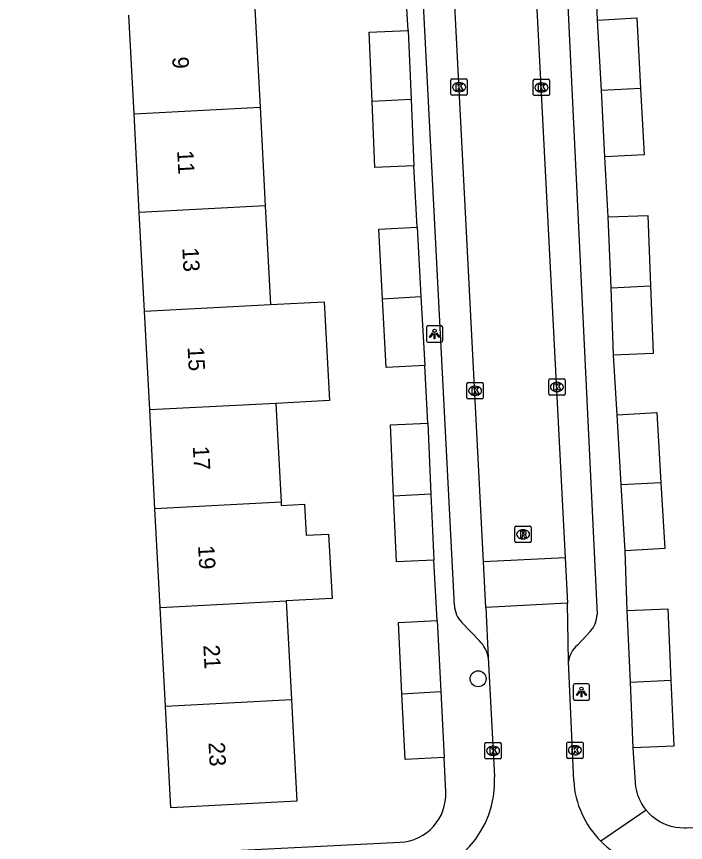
# Model space of a CAD drawing. Extents: x 161084 to 161928, y 385355 to 386522.
# Drawn here: x 161364.7 to 161405.7, y 385655.3 to 385705.9 of the extents above; entities that cross this region are included whole.
import ezdxf

# ---------------------------------------------------------------- set-up
doc = ezdxf.new("R2010")
doc.units = 0
for name, color, linetype in [('IMGEO_Boom', 7, 'Continuous'), ('IMGEO_Kolk', 7, 'Continuous'), ('IMGEO_Lichtpunt', 7, 'Continuous'), ('IMGEO_Pand', 7, 'Continuous'), ('IMGEO_Pand_nummerreeks', 7, 'Continuous'), ('IMGEO_Rijbaan_lokaal_open', 7, 'Continuous'), ('IMGEO_Rioolput', 7, 'Continuous'), ('IMGEO_Voetpad_open', 7, 'Continuous')]:
    doc.layers.add(name, color=color, linetype=linetype)

msp = doc.modelspace()

# ---------------------------------------------------------------- linework, layer by layer
at = {"layer": 'IMGEO_Boom'}
msp.add_circle((161392.96, 385665.309), 0.489, dxfattribs=at)
at = {"layer": 'IMGEO_Kolk'}
for p, q in [((161391.293, 385701.148), (161391.293, 385702)), ((161391.368, 385702.074), (161392.22, 385702.074)), ((161391.781, 385701.854), (161391.806, 385701.854)), ((161392.294, 385702), (161392.294, 385701.148)), ((161396.34, 385701.129), (161396.34, 385701.981)), ((161396.415, 385702.055), (161397.267, 385702.055)), ((161396.828, 385701.835), (161396.853, 385701.835)), ((161397.341, 385701.981), (161397.341, 385701.129)), ((161391.804, 385701.294), (161391.779, 385701.294)), ((161396.851, 385701.275), (161396.826, 385701.275)), ((161392.22, 385701.074), (161391.368, 385701.074)), ((161397.267, 385701.055), (161396.415, 385701.055)), ((161392.269, 385682.538), (161392.269, 385683.39)), ((161392.344, 385683.464), (161393.196, 385683.464)), ((161393.27, 385683.39), (161393.27, 385682.538)), ((161397.288, 385682.767), (161397.288, 385683.619)), ((161397.363, 385683.693), (161398.215, 385683.693)), ((161397.776, 385683.473), (161397.801, 385683.473)), ((161398.289, 385683.619), (161398.289, 385682.767)), ((161392.757, 385683.244), (161392.782, 385683.244)), ((161397.799, 385682.913), (161397.774, 385682.913)), ((161393.196, 385682.464), (161392.344, 385682.464)), ((161392.78, 385682.684), (161392.755, 385682.684)), ((161398.215, 385682.693), (161397.363, 385682.693)), ((161393.376, 385660.471), (161393.376, 385661.323)), ((161393.451, 385661.397), (161394.303, 385661.397)), ((161393.864, 385661.177), (161393.889, 385661.177)), ((161394.377, 385661.323), (161394.377, 385660.471)), ((161398.394, 385660.502), (161398.394, 385661.354)), ((161398.469, 385661.428), (161399.321, 385661.428)), ((161398.882, 385661.208), (161398.907, 385661.208)), ((161399.395, 385661.354), (161399.395, 385660.502)), ((161393.887, 385660.617), (161393.862, 385660.617)), ((161398.905, 385660.648), (161398.88, 385660.648)), ((161394.303, 385660.397), (161393.451, 385660.397)), ((161399.321, 385660.428), (161398.469, 385660.428))]:
    msp.add_line(p, q, dxfattribs=at)
for points in [[(161391.293, 385701.148), (161391.293, 385702)], [(161391.368, 385702.074), (161392.22, 385702.074)], [(161391.614, 385701.774), (161391.737, 385701.774), (161391.737, 385701.623), (161391.867, 385701.774), (161392.031, 385701.774), (161391.885, 385701.623), (161392.038, 385701.374), (161391.886, 385701.374), (161391.801, 385701.538), (161391.737, 385701.471), (161391.737, 385701.374), (161391.614, 385701.374), (161391.614, 385701.774)], [(161392.294, 385702), (161392.294, 385701.148)], [(161396.34, 385701.129), (161396.34, 385701.981)], [(161396.415, 385702.055), (161397.267, 385702.055)], [(161396.661, 385701.755), (161396.784, 385701.755), (161396.784, 385701.604), (161396.914, 385701.755), (161397.078, 385701.755), (161396.932, 385701.604), (161397.085, 385701.355), (161396.933, 385701.355), (161396.848, 385701.519), (161396.784, 385701.452), (161396.784, 385701.355), (161396.661, 385701.355), (161396.661, 385701.755)], [(161397.341, 385701.981), (161397.341, 385701.129)], [(161392.22, 385701.074), (161391.368, 385701.074)], [(161397.267, 385701.055), (161396.415, 385701.055)], [(161392.269, 385682.538), (161392.269, 385683.39)], [(161392.344, 385683.464), (161393.196, 385683.464)], [(161393.27, 385683.39), (161393.27, 385682.538)], [(161397.288, 385682.767), (161397.288, 385683.619)], [(161397.363, 385683.693), (161398.215, 385683.693)], [(161397.609, 385683.393), (161397.732, 385683.393), (161397.732, 385683.242), (161397.862, 385683.393), (161398.026, 385683.393), (161397.88, 385683.242), (161398.033, 385682.993), (161397.881, 385682.993), (161397.796, 385683.157), (161397.732, 385683.09), (161397.732, 385682.993), (161397.609, 385682.993), (161397.609, 385683.393)], [(161398.289, 385683.619), (161398.289, 385682.767)], [(161392.59, 385683.164), (161392.713, 385683.164), (161392.713, 385683.013), (161392.843, 385683.164), (161393.007, 385683.164), (161392.861, 385683.013), (161393.014, 385682.764), (161392.862, 385682.764), (161392.777, 385682.928), (161392.713, 385682.861), (161392.713, 385682.764), (161392.59, 385682.764), (161392.59, 385683.164)], [(161393.196, 385682.464), (161392.344, 385682.464)], [(161398.215, 385682.693), (161397.363, 385682.693)], [(161393.376, 385660.471), (161393.376, 385661.323)], [(161393.451, 385661.397), (161394.303, 385661.397)], [(161394.377, 385661.323), (161394.377, 385660.471)], [(161398.394, 385660.502), (161398.394, 385661.354)], [(161398.469, 385661.428), (161399.321, 385661.428)], [(161398.715, 385661.128), (161398.838, 385661.128), (161398.838, 385660.977), (161398.968, 385661.128), (161399.132, 385661.128), (161398.986, 385660.977), (161399.139, 385660.728), (161398.987, 385660.728), (161398.902, 385660.892), (161398.838, 385660.825), (161398.838, 385660.728), (161398.715, 385660.728), (161398.715, 385661.128)], [(161399.395, 385661.354), (161399.395, 385660.502)], [(161393.697, 385661.097), (161393.82, 385661.097), (161393.82, 385660.946), (161393.95, 385661.097), (161394.114, 385661.097), (161393.968, 385660.946), (161394.121, 385660.697), (161393.969, 385660.697), (161393.884, 385660.861), (161393.82, 385660.794), (161393.82, 385660.697), (161393.697, 385660.697), (161393.697, 385661.097)], [(161394.303, 385660.397), (161393.451, 385660.397)], [(161399.321, 385660.428), (161398.469, 385660.428)]]:
    msp.add_lwpolyline(points, dxfattribs=at)
for centre, start, end in [((161391.37, 385701.998), 91.552, 178.448), ((161391.37, 385701.998), 91.552, 178.448), ((161392.218, 385701.998), 1.552, 88.448), ((161392.218, 385701.998), 1.552, 88.448), ((161396.417, 385701.979), 91.552, 178.448), ((161396.417, 385701.979), 91.552, 178.448), ((161397.265, 385701.979), 1.552, 88.448), ((161397.265, 385701.979), 1.552, 88.448), ((161391.37, 385701.15), 181.552, 268.448), ((161391.37, 385701.15), 181.552, 268.448), ((161392.218, 385701.15), 271.552, 358.448), ((161392.218, 385701.15), 271.552, 358.448), ((161396.417, 385701.131), 181.552, 268.448), ((161396.417, 385701.131), 181.552, 268.448), ((161397.265, 385701.131), 271.552, 358.448), ((161397.265, 385701.131), 271.552, 358.448), ((161392.346, 385683.388), 91.552, 178.448), ((161392.346, 385683.388), 91.552, 178.448), ((161393.194, 385683.388), 1.552, 88.448), ((161393.194, 385683.388), 1.552, 88.448), ((161397.365, 385683.617), 91.552, 178.448), ((161397.365, 385683.617), 91.552, 178.448), ((161398.213, 385683.617), 1.552, 88.448), ((161398.213, 385683.617), 1.552, 88.448), ((161392.346, 385682.54), 181.552, 268.448), ((161392.346, 385682.54), 181.552, 268.448), ((161393.194, 385682.54), 271.552, 358.448), ((161393.194, 385682.54), 271.552, 358.448), ((161397.365, 385682.769), 181.552, 268.448), ((161397.365, 385682.769), 181.552, 268.448), ((161398.213, 385682.769), 271.552, 358.448), ((161398.213, 385682.769), 271.552, 358.448), ((161393.453, 385661.321), 91.552, 178.448), ((161393.453, 385661.321), 91.552, 178.448), ((161394.301, 385661.321), 1.552, 88.448), ((161394.301, 385661.321), 1.552, 88.448), ((161398.471, 385661.352), 91.552, 178.448), ((161398.471, 385661.352), 91.552, 178.448), ((161399.319, 385661.352), 1.552, 88.448), ((161399.319, 385661.352), 1.552, 88.448), ((161393.453, 385660.473), 181.552, 268.448), ((161393.453, 385660.473), 181.552, 268.448), ((161394.301, 385660.473), 271.552, 358.448), ((161394.301, 385660.473), 271.552, 358.448), ((161398.471, 385660.504), 181.552, 268.448), ((161398.471, 385660.504), 181.552, 268.448), ((161399.319, 385660.504), 271.552, 358.448), ((161399.319, 385660.504), 271.552, 358.448)]:
    msp.add_arc(centre, 0.0765, start, end, dxfattribs=at)
for centre, major_axis, ratio, start_param, end_param in [((161391.78, 385701.574), (-0.387, 0.002), 0.722429, 4.712389, 7.853982), ((161391.805, 385701.574), (-0.39, 0.002), 0.717154, 1.570796, 4.712389), ((161396.827, 385701.555), (-0.387, 0.002), 0.722429, 4.712389, 7.853982), ((161396.852, 385701.555), (-0.39, 0.002), 0.717154, 1.570796, 4.712389), ((161397.775, 385683.193), (-0.387, 0.002), 0.722429, 4.712389, 7.853982), ((161397.8, 385683.193), (-0.39, 0.002), 0.717154, 1.570796, 4.712389), ((161392.756, 385682.964), (-0.387, 0.002), 0.722429, 4.712389, 7.853982), ((161392.781, 385682.964), (-0.39, 0.002), 0.717154, 1.570796, 4.712389), ((161393.863, 385660.897), (-0.387, 0.002), 0.722429, 4.712389, 7.853982), ((161393.888, 385660.897), (-0.39, 0.002), 0.717154, 1.570796, 4.712389), ((161398.881, 385660.928), (-0.387, 0.002), 0.722429, 4.712389, 7.853982), ((161398.906, 385660.928), (-0.39, 0.002), 0.717154, 1.570796, 4.712389)]:
    msp.add_ellipse(centre, major_axis=major_axis, ratio=ratio, start_param=start_param, end_param=end_param, dxfattribs=at)
at = {"layer": 'IMGEO_Lichtpunt'}
for p, q in [((161390.694, 385686.939), (161389.886, 385686.939)), ((161390.694, 385686.939), (161389.886, 385686.939)), ((161389.792, 385686.844), (161389.792, 385686.037)), ((161389.792, 385686.844), (161389.792, 385686.037)), ((161390.788, 385686.037), (161390.788, 385686.844)), ((161390.788, 385686.037), (161390.788, 385686.844)), ((161389.886, 385685.943), (161390.694, 385685.943)), ((161389.886, 385685.943), (161390.694, 385685.943)), ((161398.793, 385664.905), (161398.793, 385664.098)), ((161398.793, 385664.905), (161398.793, 385664.098)), ((161399.695, 385665), (161398.887, 385665)), ((161399.695, 385665), (161398.887, 385665)), ((161399.789, 385664.098), (161399.789, 385664.905)), ((161399.789, 385664.098), (161399.789, 385664.905)), ((161398.887, 385664.004), (161399.695, 385664.004)), ((161398.887, 385664.004), (161399.695, 385664.004))]:
    msp.add_line(p, q, dxfattribs=at)
for points in [[(161390.166, 385686.508), (161390.205, 385686.48), (161390.017, 385686.218), (161389.979, 385686.245), (161390.166, 385686.508)], [(161390.268, 385686.46), (161390.315, 385686.46), (161390.315, 385686.138), (161390.268, 385686.138), (161390.268, 385686.46)], [(161390.378, 385686.48), (161390.416, 385686.507), (161390.603, 385686.245), (161390.564, 385686.217), (161390.378, 385686.48)], [(161399.167, 385664.569), (161399.206, 385664.541), (161399.018, 385664.279), (161398.98, 385664.306), (161399.167, 385664.569)], [(161399.269, 385664.521), (161399.316, 385664.521), (161399.316, 385664.199), (161399.269, 385664.199), (161399.269, 385664.521)], [(161399.379, 385664.541), (161399.417, 385664.568), (161399.604, 385664.306), (161399.565, 385664.278), (161399.379, 385664.541)]]:
    msp.add_lwpolyline(points, dxfattribs=at)
for centre in [(161390.291, 385686.642), (161399.292, 385664.703)]:
    msp.add_circle(centre, 0.0994, dxfattribs=at)
for centre, start, end in [((161389.886, 385686.844), 90, 180), ((161389.886, 385686.844), 90, 180), ((161390.694, 385686.844), 0, 90), ((161390.694, 385686.844), 0, 90), ((161389.886, 385686.037), 180, 270), ((161389.886, 385686.037), 180, 270), ((161390.694, 385686.037), 270, 0), ((161390.694, 385686.037), 270, 360), ((161398.887, 385664.905), 90, 180), ((161398.887, 385664.905), 90, 180), ((161399.695, 385664.905), 0, 90), ((161399.695, 385664.905), 0, 90), ((161398.887, 385664.098), 180, 270), ((161398.887, 385664.098), 180, 270), ((161399.695, 385664.098), 270, 0), ((161399.695, 385664.098), 270, 360)]:
    msp.add_arc(centre, 0.0946, start, end, dxfattribs=at)
at = {"layer": 'IMGEO_Pand'}
for points in [[(161379.275, 385706.399), (161379.596, 385700.347)], [(161371.869, 385699.939), (161371.549, 385705.991)], [(161400.284, 385705.685), (161402.687, 385705.811), (161402.914, 385701.486)], [(161400.511, 385701.364), (161400.284, 385705.685)], [(161386.463, 385700.71), (161386.288, 385704.943), (161388.675, 385705.041)], [(161388.675, 385705.041), (161388.849, 385700.836)], [(161402.914, 385701.486), (161400.511, 385701.364)], [(161400.724, 385697.298), (161400.511, 385701.364)], [(161402.914, 385701.486), (161403.127, 385697.424), (161400.724, 385697.298)], [(161386.463, 385700.71), (161388.849, 385700.836)], [(161389.019, 385696.743), (161386.632, 385696.645), (161386.463, 385700.71)], [(161388.849, 385700.836), (161389.019, 385696.743)], [(161371.869, 385699.939), (161379.596, 385700.347)], [(161379.596, 385700.347), (161379.916, 385694.296)], [(161372.189, 385693.888), (161371.869, 385699.939)], [(161379.916, 385694.296), (161372.189, 385693.888)], [(161379.916, 385694.296), (161380.237, 385688.244)], [(161372.51, 385687.836), (161372.189, 385693.888)], [(161400.936, 385693.616), (161403.358, 385693.71), (161403.525, 385689.4)], [(161401.104, 385689.278), (161400.936, 385693.616)], [(161387.099, 385688.606), (161386.868, 385692.866), (161389.224, 385692.993)], [(161389.224, 385692.993), (161389.455, 385688.731)], [(161401.104, 385689.278), (161403.525, 385689.4)], [(161401.264, 385685.149), (161401.104, 385689.278)], [(161403.525, 385689.4), (161403.687, 385685.243), (161401.264, 385685.149)], [(161387.099, 385688.606), (161389.455, 385688.731)], [(161389.684, 385684.509), (161387.328, 385684.382), (161387.099, 385688.606)], [(161389.455, 385688.731), (161389.684, 385684.509)], [(161372.51, 385687.836), (161380.237, 385688.244)], [(161380.237, 385688.244), (161383.52, 385688.418), (161383.84, 385682.366), (161380.557, 385682.192)], [(161372.83, 385681.784), (161372.51, 385687.836)], [(161380.557, 385682.192), (161372.83, 385681.784)], [(161380.557, 385682.192), (161380.878, 385676.141)], [(161373.151, 385675.733), (161372.83, 385681.784)], [(161401.483, 385681.488), (161403.919, 385681.628), (161404.166, 385677.314)], [(161401.729, 385677.191), (161401.483, 385681.488)], [(161387.78, 385676.505), (161387.588, 385680.867), (161389.868, 385680.967)], [(161389.868, 385680.967), (161390.059, 385676.626)], [(161404.166, 385677.314), (161401.729, 385677.191)], [(161401.961, 385673.147), (161401.729, 385677.191)], [(161404.166, 385677.314), (161404.397, 385673.287), (161401.961, 385673.147)], [(161390.059, 385676.626), (161387.78, 385676.505)], [(161390.238, 385672.579), (161387.958, 385672.479), (161387.78, 385676.505)], [(161390.059, 385676.626), (161390.238, 385672.579)], [(161380.878, 385676.141), (161373.151, 385675.733)], [(161380.878, 385676.141), (161380.889, 385675.932), (161382.315, 385676.007), (161382.415, 385674.111), (161383.796, 385674.183), (161384.004, 385670.237), (161381.198, 385670.089)], [(161373.471, 385669.681), (161373.151, 385675.733)], [(161373.471, 385669.681), (161381.198, 385670.089)], [(161381.198, 385670.089), (161381.519, 385664.038)], [(161373.791, 385663.63), (161373.471, 385669.681)], [(161402.098, 385669.486), (161404.579, 385669.595), (161404.771, 385665.228)], [(161402.291, 385665.103), (161402.098, 385669.486)], [(161388.287, 385664.395), (161388.073, 385668.762), (161390.458, 385668.878)], [(161390.458, 385668.878), (161390.671, 385664.521)], [(161402.291, 385665.103), (161404.771, 385665.228)], [(161404.771, 385665.228), (161404.95, 385661.177), (161402.469, 385661.068)], [(161402.469, 385661.068), (161402.291, 385665.103)], [(161388.287, 385664.395), (161390.671, 385664.521)], [(161390.869, 385660.483), (161388.484, 385660.366), (161388.287, 385664.395)], [(161390.671, 385664.521), (161390.869, 385660.483)], [(161381.519, 385664.038), (161381.584, 385662.807), (161381.848, 385657.813), (161374.121, 385657.403), (161373.791, 385663.63)], [(161373.791, 385663.63), (161381.519, 385664.038)]]:
    msp.add_lwpolyline(points, dxfattribs=at)
at = {"layer": 'IMGEO_Rijbaan_lokaal_open'}
for points in [[(161395.274, 385731.281), (161398.285, 385672.728)], [(161393.28, 385672.47), (161390.284, 385730.795)], [(161398.285, 385672.728), (161393.28, 385672.47)], [(161393.423, 385669.684), (161393.28, 385672.47)], [(161398.285, 385672.728), (161398.428, 385669.942)], [(161398.428, 385669.942), (161393.423, 385669.684)], [(161398.5, 385666.359), (161398.428, 385669.942)], [(161393.423, 385669.684), (161393.58, 385666.612)], [(161393.58, 385666.612), (161393.956, 385659.301)], [(161398.817, 385659.048), (161398.5, 385666.359)]]:
    msp.add_lwpolyline(points, dxfattribs=at)
for centre, radius, start, end in [((161388.005, 385659.009), 5.958, 273.248, 2.808), ((161404.516, 385659.389), 5.709, 183.4224, 224.9026), ((161404.514, 385659.385), 5.705, 224.8914, 266.3452)]:
    msp.add_arc(centre, radius, start, end, dxfattribs=at)
at = {"layer": 'IMGEO_Rioolput'}
for p, q in [((161395.211, 385673.738), (161395.211, 385674.59)), ((161395.286, 385674.664), (161396.138, 385674.664)), ((161395.699, 385674.444), (161395.724, 385674.444)), ((161396.212, 385674.59), (161396.212, 385673.738)), ((161395.722, 385673.884), (161395.697, 385673.884)), ((161396.138, 385673.664), (161395.286, 385673.664))]:
    msp.add_line(p, q, dxfattribs=at)
for points in [[(161395.211, 385673.738), (161395.211, 385674.59)], [(161395.286, 385674.664), (161396.138, 385674.664)], [(161395.8, 385674.362), (161395.548, 385674.364), (161395.548, 385673.964)], [(161395.726, 385674.283), (161395.672, 385674.283), (161395.672, 385674.202)], [(161396.212, 385674.59), (161396.212, 385673.738)], [(161395.548, 385673.964), (161395.672, 385673.964), (161395.672, 385674.126), (161395.683, 385674.126)], [(161395.672, 385674.202), (161395.724, 385674.202)], [(161395.73, 385674.097), (161395.801, 385673.964), (161395.941, 385673.964), (161395.876, 385674.09)], [(161396.138, 385673.664), (161395.286, 385673.664)]]:
    msp.add_lwpolyline(points, dxfattribs=at)
for centre, radius, start, end in [((161395.288, 385674.588), 0.0765, 91.552, 178.448), ((161395.288, 385674.588), 0.0765, 91.552, 178.448), ((161395.732, 385674.187), 0.0964, 77.0061, 93.1865), ((161395.746, 385674.244), 0.0378, 276.6634, 79.6772), ((161395.799, 385674.252), 0.109, 350.3612, 89.416), ((161396.136, 385674.588), 0.0765, 1.552, 88.448), ((161396.136, 385674.588), 0.0765, 1.552, 88.448), ((161395.682, 385674.073), 0.0533, 26.0293, 88.6989), ((161395.708, 385674.391), 0.19, 274.7715, 282.9687), ((161395.797, 385674.252), 0.112, 277.5842, 350.9817), ((161395.781, 385674.037), 0.108, 29.5134, 73.7905), ((161395.288, 385673.74), 0.0765, 181.552, 268.448), ((161395.288, 385673.74), 0.0765, 181.552, 268.448), ((161396.136, 385673.74), 0.0765, 271.552, 358.448), ((161396.136, 385673.74), 0.0765, 271.552, 358.448)]:
    msp.add_arc(centre, radius, start, end, dxfattribs=at)
for centre, major_axis, ratio, start_param, end_param in [((161395.698, 385674.164), (-0.387, 0.002), 0.722429, 4.712389, 7.853982), ((161395.723, 385674.164), (-0.39, 0.002), 0.717154, 1.570796, 4.712389)]:
    msp.add_ellipse(centre, major_axis=major_axis, ratio=ratio, start_param=start_param, end_param=end_param, dxfattribs=at)
at = {"layer": 'IMGEO_Voetpad_open'}
for points in [[(161395.274, 385731.281), (161395.294, 385731.127), (161395.327, 385730.976), (161395.374, 385730.828), (161395.434, 385730.685), (161395.506, 385730.548), (161395.59, 385730.418), (161395.686, 385730.296), (161395.76, 385730.215), (161396.868, 385729.068), (161396.987, 385728.933), (161397.093, 385728.789), (161397.186, 385728.635), (161397.264, 385728.475), (161397.328, 385728.307), (161397.377, 385728.135), (161397.41, 385727.959), (161397.427, 385727.781), (161400.248, 385669.245)], [(161391.505, 385669.795), (161388.519, 385727.644)], [(161400.284, 385705.685), (161400.127, 385709.302)], [(161388.675, 385705.041), (161388.436, 385708.777)], [(161400.936, 385693.616), (161400.724, 385697.298)], [(161389.224, 385692.993), (161389.019, 385696.743)], [(161401.483, 385681.488), (161401.264, 385685.149)], [(161389.868, 385680.967), (161389.684, 385684.509)], [(161402.098, 385669.486), (161401.961, 385673.147)], [(161390.458, 385668.878), (161390.238, 385672.579)], [(161393.053, 385667.628), (161391.954, 385668.765)], [(161399.819, 385668.208), (161399.043, 385667.379)], [(161403.264, 385657.253), (161403.107, 385657.466), (161402.969, 385657.692), (161402.852, 385657.929), (161402.756, 385658.177), (161402.683, 385658.431), (161402.633, 385658.691), (161402.607, 385658.955), (161402.469, 385661.068)], [(161390.975, 385658.38), (161390.869, 385660.483)], [(161403.264, 385657.253), (161400.472, 385655.359)], [(161423.333, 385657.052), (161413.445, 385656.551), (161405.714, 385656.16), (161405.58, 385656.156), (161405.316, 385656.167), (161405.053, 385656.201), (161404.794, 385656.258), (161404.542, 385656.339), (161404.298, 385656.441), (161404.063, 385656.565), (161403.841, 385656.709), (161403.633, 385656.873), (161403.44, 385657.055), (161403.264, 385657.253)], [(161362.696, 385656.941), (161362.721, 385656.681), (161362.769, 385656.425), (161362.839, 385656.174), (161362.932, 385655.93), (161363.046, 385655.696), (161363.181, 385655.473), (161363.335, 385655.262), (161363.507, 385655.067), (161363.696, 385654.887), (161363.9, 385654.725), (161364.118, 385654.582), (161364.348, 385654.459), (161364.588, 385654.357), (161364.836, 385654.277), (161365.091, 385654.219), (161365.349, 385654.184), (161365.609, 385654.173), (161365.749, 385654.176), (161379.269, 385654.847), (161388.176, 385655.289)]]:
    msp.add_lwpolyline(points, dxfattribs=at)
for centre, radius, start, end in [((161393.1, 385669.877), 1.597, 182.9541, 224.1528), ((161398.747, 385669.259), 1.501, 315.5778, 359.4731), ((161391.596, 385666.228), 2.02, 10.9616, 43.87), ((161400.079, 385666.173), 1.59, 130.6585, 173.284), ((161388.027, 385658.237), 2.952, 272.8989, 2.7774)]:
    msp.add_arc(centre, radius, start, end, dxfattribs=at)

# ---------------------------------------------------------------- texts
at = {"layer": 'IMGEO_Pand_nummerreeks'}
for s, rotation, p in [('9', 273.0305, (161374.209, 385703.416)), ('11', 273.0305, (161374.511, 385697.681)), ('13', 273.0305, (161374.827, 385691.714)), ('15', 273.0307, (161375.15, 385685.633)), ('17', 273.0305, (161375.471, 385679.553)), ('19', 273.0307, (161375.794, 385673.472)), ('21', 273.0305, (161376.116, 385667.369)), ('23', 273.0305, (161376.432, 385661.402))]:
    msp.add_text(s, height=1, rotation=rotation, dxfattribs=at).set_placement(p)

doc.saveas('drawing.dxf')
